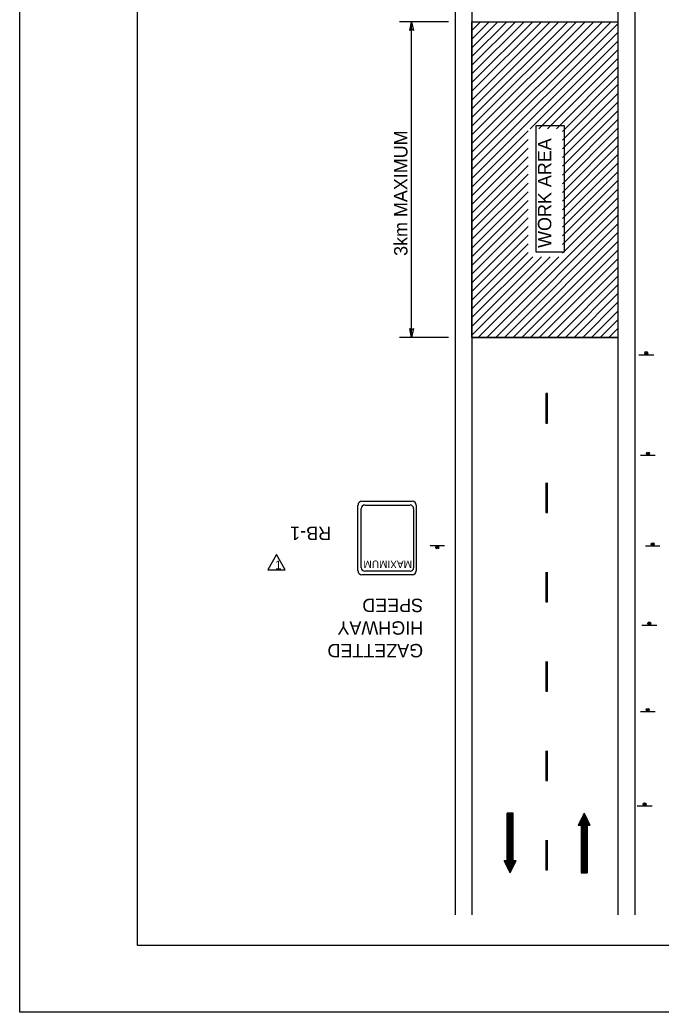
# Model space of a CAD drawing. Extents: x 2195 to 2411, y 202 to 481.
# Drawn here: x 2195.4 to 2299.5, y 201.9 to 363.1 of the extents above; entities that cross this region are included whole.
import ezdxf

# ---------------------------------------------------------------- set-up
doc = ezdxf.new("R2010")
doc.units = 0
for name, color, linetype in [('Level 1', 7, 'Continuous'), ('Level 10', 7, 'Continuous'), ('Level 2', 7, 'Continuous'), ('Level 44', 7, 'Continuous'), ('Level 60', 7, 'Continuous')]:
    doc.layers.add(name, color=color, linetype=linetype)

msp = doc.modelspace()

# ---------------------------------------------------------------- linework, layer by layer
at = {"layer": 'Level 1'}
msp.add_lwpolyline([(2237.07, 276.21), (2235.65, 273.74), (2238.49, 273.74)], close=True, dxfattribs=at)
at = {"layer": 'Level 10'}
for p, q in [((2266.09, 465.71), (2266.09, 217.7)), ((2268.81, 465.71), (2268.81, 217.7)), ((2292.52, 447.88), (2292.52, 311.49)), ((2295.26, 447.88), (2295.26, 217.7)), ((2265.02, 362.78), (2257.05, 362.78)), ((2259.01, 311.5), (2259.01, 362.78)), ((2268.81, 362.78), (2292.52, 362.78)), ((2280.42, 362.78), (2292.52, 362.78)), ((2292.52, 362.78), (2292.52, 217.7)), ((2265.02, 311.5), (2257.05, 311.5)), ((2268.81, 311.49), (2292.52, 311.49)), ((2274.55, 226.44), (2274.55, 234.19)), ((2275.52, 234.19), (2274.55, 234.19)), ((2274.55, 225.48), (2274.55, 234.19)), ((2274.67, 225.24), (2274.67, 234.19)), ((2274.79, 224.99), (2274.79, 234.19)), ((2274.92, 224.75), (2274.92, 234.19)), ((2275.04, 224.51), (2275.04, 234.19)), ((2275.16, 224.75), (2275.16, 234.19)), ((2275.28, 224.99), (2275.28, 234.19)), ((2275.4, 225.24), (2275.4, 234.19)), ((2275.52, 226.44), (2275.52, 234.19)), ((2275.52, 225.48), (2275.52, 234.19)), ((2287.03, 234.22), (2286.06, 232.28)), ((2286.79, 233.74), (2286.79, 224.54)), ((2286.91, 233.98), (2286.91, 224.54)), ((2287.03, 234.22), (2287.03, 224.54)), ((2287.03, 234.22), (2287.99, 232.28)), ((2287.15, 233.98), (2287.15, 224.54)), ((2287.27, 233.74), (2287.27, 224.54)), ((2286.06, 232.28), (2286.54, 232.28)), ((2286.18, 232.53), (2286.18, 232.28)), ((2286.3, 232.77), (2286.3, 232.28)), ((2286.42, 233.01), (2286.42, 232.28)), ((2286.54, 233.25), (2286.54, 224.54)), ((2286.54, 232.28), (2286.54, 224.54)), ((2286.66, 233.49), (2286.66, 224.54)), ((2287.39, 233.49), (2287.39, 224.54)), ((2287.51, 233.25), (2287.51, 224.54)), ((2287.51, 232.28), (2287.51, 224.54)), ((2287.51, 232.28), (2287.99, 232.28)), ((2287.63, 233.01), (2287.63, 232.28)), ((2287.75, 232.77), (2287.75, 232.28)), ((2287.87, 232.53), (2287.87, 232.28)), ((2275.04, 224.51), (2274.07, 226.44)), ((2274.55, 226.44), (2274.07, 226.44)), ((2274.19, 226.2), (2274.19, 226.44)), ((2274.31, 225.96), (2274.31, 226.44)), ((2274.43, 225.72), (2274.43, 226.44)), ((2275.04, 224.51), (2276, 226.44)), ((2276, 226.44), (2275.52, 226.44)), ((2275.64, 225.72), (2275.64, 226.44)), ((2275.76, 225.96), (2275.76, 226.44)), ((2275.88, 226.2), (2275.88, 226.44)), ((2286.54, 224.54), (2287.51, 224.54))]:
    msp.add_line(p, q, dxfattribs=at)
for points in [[(2259.01, 362.78), (2259.31, 361.33), (2259.01, 361.57), (2258.71, 361.33)], [(2268.81, 362.78), (2292.52, 362.78), (2292.52, 311.49), (2268.81, 311.49)], [(2268.81, 362.78), (2292.52, 362.78), (2292.52, 311.49), (2268.81, 311.49)], [(2283.87, 345.85), (2279.2, 345.85), (2279.2, 325.37), (2283.87, 325.37)], [(2283.87, 345.85), (2279.2, 345.85), (2279.2, 325.37), (2283.87, 325.37)], [(2259.01, 311.5), (2258.71, 312.95), (2259.01, 312.71), (2259.31, 312.95)]]:
    msp.add_lwpolyline(points, close=True, dxfattribs=at)
at = {"layer": 'Level 2'}
for p, q in [((2268.81, 362.78), (2268.81, 362.78)), ((2268.81, 361.37), (2270.22, 362.78)), ((2268.81, 359.95), (2271.64, 362.78)), ((2268.81, 358.54), (2273.05, 362.78)), ((2268.81, 357.12), (2274.47, 362.78)), ((2268.81, 355.71), (2275.88, 362.78)), ((2268.81, 354.3), (2277.3, 362.78)), ((2268.81, 352.88), (2278.71, 362.78)), ((2268.81, 351.47), (2280.12, 362.78)), ((2268.81, 350.05), (2281.54, 362.78)), ((2268.81, 348.64), (2282.95, 362.78)), ((2268.81, 347.22), (2284.37, 362.78)), ((2268.81, 345.81), (2285.78, 362.78)), ((2268.81, 344.39), (2287.2, 362.78)), ((2268.81, 342.98), (2288.61, 362.78)), ((2268.81, 341.57), (2290.02, 362.78)), ((2268.81, 340.15), (2291.44, 362.78)), ((2268.81, 338.74), (2292.52, 362.45)), ((2268.81, 337.32), (2292.52, 361.03)), ((2278.28, 345.38), (2292.52, 359.62)), ((2279.7, 345.38), (2292.52, 358.2)), ((2281.11, 345.38), (2292.52, 356.79)), ((2282.53, 345.38), (2292.52, 355.38)), ((2283.5, 344.94), (2292.52, 353.96)), ((2283.5, 343.53), (2292.52, 352.55)), ((2283.5, 342.12), (2292.52, 351.13)), ((2283.5, 340.7), (2292.52, 349.72)), ((2283.5, 339.29), (2292.52, 348.31)), ((2283.5, 337.87), (2292.52, 346.89)), ((2268.81, 335.91), (2277.96, 345.06)), ((2283.5, 336.46), (2292.52, 345.48)), ((2268.81, 334.5), (2277.96, 343.64)), ((2283.5, 335.05), (2292.52, 344.06)), ((2268.81, 333.08), (2277.96, 342.23)), ((2283.5, 333.63), (2292.52, 342.65)), ((2268.81, 331.67), (2277.96, 340.81)), ((2283.5, 332.22), (2292.52, 341.23)), ((2268.81, 330.25), (2277.96, 339.4)), ((2283.5, 330.8), (2292.52, 339.82)), ((2268.81, 328.84), (2277.96, 337.99)), ((2283.5, 329.39), (2292.52, 338.41)), ((2283.5, 327.98), (2292.52, 336.99)), ((2268.81, 327.43), (2277.96, 336.57)), ((2283.5, 326.56), (2292.52, 335.58)), ((2268.81, 326.01), (2277.96, 335.16)), ((2268.81, 324.6), (2277.96, 333.74)), ((2283.5, 325.15), (2292.52, 334.16)), ((2268.81, 323.18), (2277.96, 332.33)), ((2271.26, 311.49), (2292.52, 332.75)), ((2268.81, 321.77), (2277.96, 330.92)), ((2272.68, 311.49), (2292.52, 331.33)), ((2268.81, 320.35), (2277.96, 329.5)), ((2274.09, 311.49), (2292.52, 329.92)), ((2268.81, 318.94), (2277.96, 328.09)), ((2275.5, 311.49), (2292.52, 328.51)), ((2268.81, 317.53), (2277.96, 326.67)), ((2276.92, 311.49), (2292.52, 327.09)), ((2278.33, 311.49), (2292.52, 325.68)), ((2268.81, 316.11), (2277.96, 325.26)), ((2268.81, 314.7), (2278.69, 324.57)), ((2268.81, 313.28), (2280.1, 324.57)), ((2268.81, 311.87), (2281.52, 324.57)), ((2269.85, 311.49), (2282.93, 324.57)), ((2279.75, 311.49), (2292.52, 324.26)), ((2281.16, 311.49), (2292.52, 322.85)), ((2282.58, 311.49), (2292.52, 321.44)), ((2283.99, 311.49), (2292.52, 320.02)), ((2285.4, 311.49), (2292.52, 318.61)), ((2286.82, 311.49), (2292.52, 317.19)), ((2288.23, 311.49), (2292.52, 315.78)), ((2289.65, 311.49), (2292.52, 314.36)), ((2291.06, 311.49), (2292.52, 312.95)), ((2292.47, 311.49), (2292.52, 311.54)), ((2280.81, 302.39), (2280.81, 297.56)), ((2281.1, 302.39), (2280.81, 302.39)), ((2281.1, 297.56), (2281.1, 302.39)), ((2280.81, 297.56), (2281.1, 297.56)), ((2280.81, 287.88), (2280.81, 283.04)), ((2281.1, 283.04), (2281.1, 287.88)), ((2280.81, 283.04), (2281.1, 283.04)), ((2280.81, 273.37), (2280.81, 268.53)), ((2281.1, 268.53), (2281.1, 273.37)), ((2280.81, 268.53), (2281.1, 268.53)), ((2280.81, 258.85), (2280.81, 254.02)), ((2281.1, 254.02), (2281.1, 258.85)), ((2280.81, 254.02), (2281.1, 254.02)), ((2280.81, 244.34), (2280.81, 239.5)), ((2281.1, 239.5), (2281.1, 244.34)), ((2280.81, 239.5), (2281.1, 239.5)), ((2280.81, 229.83), (2280.81, 224.99)), ((2281.1, 224.99), (2281.1, 229.83)), ((2280.81, 224.99), (2281.1, 224.99))]:
    msp.add_line(p, q, dxfattribs=at)
at = {"layer": 'Level 44'}
for p, q in [((2295.92, 308.68), (2298.34, 308.68)), ((2296.18, 292.36), (2298.6, 292.36)), ((2250.31, 273.55), (2250.31, 284.23)), ((2250.95, 284.87), (2259.14, 284.87)), ((2251.41, 284.26), (2258.78, 284.26)), ((2259.77, 284.24), (2259.77, 284.23)), ((2259.77, 284.23), (2259.77, 273.55)), ((2250.84, 274.08), (2250.84, 283.69)), ((2259.35, 283.69), (2259.35, 274.08)), ((2259.35, 283.69), (2259.35, 283.69)), ((2264.36, 277.63), (2262.02, 277.63)), ((2296.99, 277.63), (2299.33, 277.63)), ((2259.14, 272.92), (2250.95, 272.92)), ((2258.78, 273.51), (2251.41, 273.51)), ((2296.4, 264.75), (2298.82, 264.75)), ((2296.17, 250.7), (2298.59, 250.7)), ((2295.66, 235.38), (2298.07, 235.38))]:
    msp.add_line(p, q, dxfattribs=at)
for centre, radius in [((2297.13, 308.95), 0.242), ((2297.13, 308.95), 0.121), ((2297.39, 292.63), 0.242), ((2297.39, 292.63), 0.121), ((2263.19, 277.37), 0.234), ((2263.19, 277.37), 0.117), ((2298.17, 277.9), 0.234), ((2298.17, 277.9), 0.117), ((2297.61, 265.02), 0.242), ((2297.61, 265.02), 0.121), ((2297.38, 250.97), 0.242), ((2297.38, 250.97), 0.121), ((2296.87, 235.65), 0.242), ((2296.87, 235.65), 0.121)]:
    msp.add_circle(centre, radius, dxfattribs=at)
for centre, radius, start, end in [((2250.95, 284.24), 0.632, 90, 180), ((2251.41, 283.7), 0.569, 90, 180), ((2258.78, 283.7), 0.569, 360, 90), ((2259.14, 284.24), 0.632, 360, 90), ((2251.41, 274.08), 0.569, 180, 270), ((2258.78, 274.08), 0.569, 270, 360), ((2250.95, 273.56), 0.632, 180, 270), ((2259.14, 273.56), 0.632, 270, 360)]:
    msp.add_arc(centre, radius, start, end, dxfattribs=at)
at = {"layer": 'Level 60'}
for points in [[(2195.4, 480.88), (2411.4, 480.88), (2411.4, 201.88), (2195.4, 201.88)], [(2214.53, 470.07), (2401.4, 470.07), (2401.4, 212.69), (2214.53, 212.69)]]:
    msp.add_lwpolyline(points, close=True, dxfattribs=at)

# ---------------------------------------------------------------- texts
at = {"layer": 'Level 1'}
msp.add_text('1', height=1.45, rotation=360, dxfattribs=at).set_placement((2236.85, 273.8))
at = {"layer": 'Level 10'}
for s, height, rotation, p in [('3km MAXIMUM', 2.1776, 90, (2258.35, 324.73)), ('WORK AREA', 2.178, 90, (2281.71, 326.03)), ('RB-1', 2.177, 180, (2245.94, 280.75)), ('SPEED', 2.177, 180, (2260.89, 269.05)), ('HIGHWAY', 2.177, 180, (2260.89, 265.38)), ('GAZETTED ', 2.177, 180, (2260.89, 261.7))]:
    msp.add_text(s, height=height, rotation=rotation, dxfattribs=at).set_placement(p)
at = {"layer": 'Level 44'}
msp.add_text('MAXIMUM', height=1.221, rotation=180, dxfattribs=at).set_placement((2259.09, 275.24))

doc.saveas('drawing.dxf')
